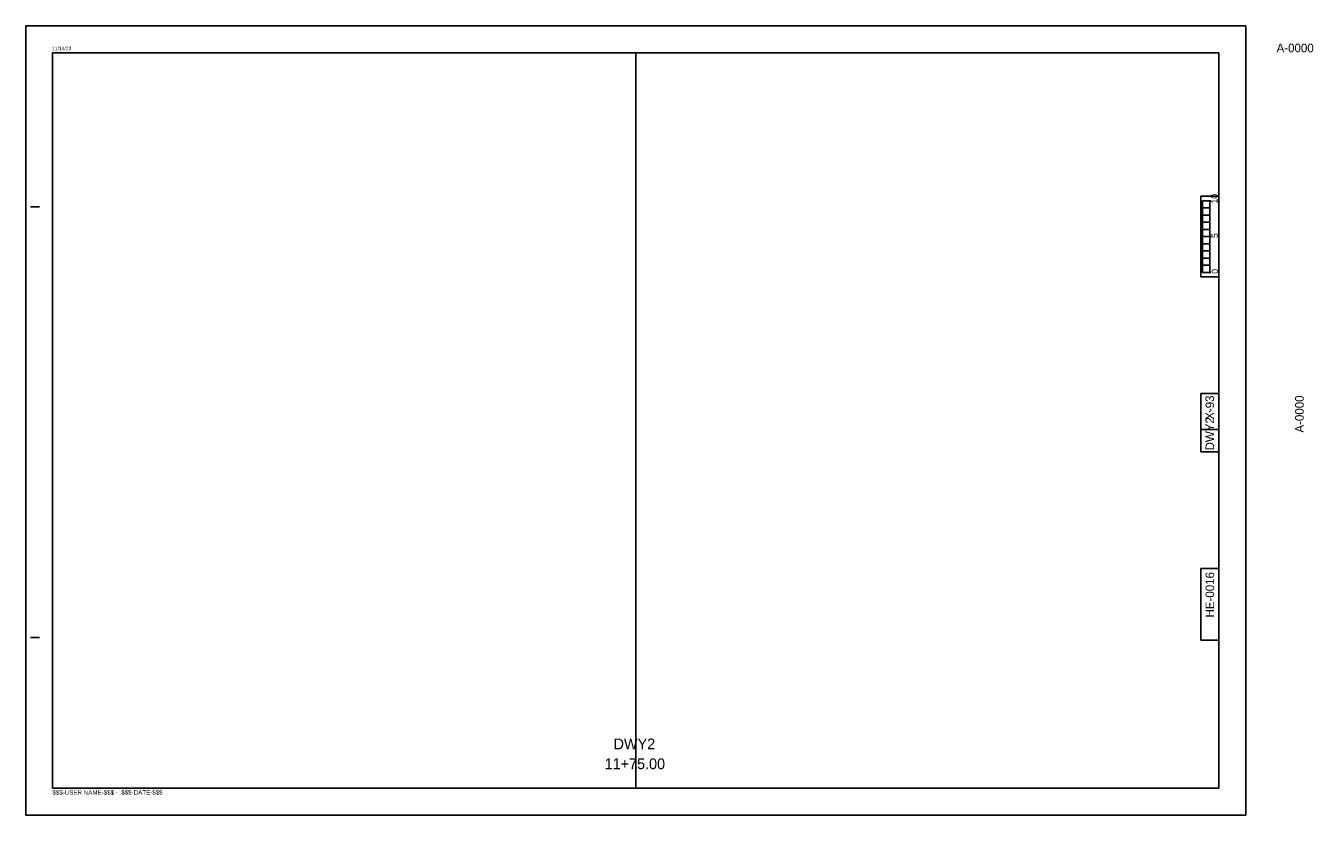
# Model space of a CAD drawing. Extents: x -2.69 to 2.99, y 0 to 1.83.
# Drawn here: x 0 to 2.99, y 0 to 1.833 of the extents above; entities that cross this region are included whole.
import ezdxf

# ---------------------------------------------------------------- set-up
doc = ezdxf.new("R2010")
doc.units = 0
for name, color, linetype in [('P_NCDOT_XS_Sheet_Alignment_Station_Label', 7, 'Continuous'), ('Sheet_Cross_Section_Scale_CELL', 7, 'Continuous'), ('Sheet_Plan_CELL', 7, 'Continuous'), ('Sheet_RDY_XS_Number', 7, 'Continuous'), ('Sheet_RDY_XS_Project_Number', 7, 'Continuous'), ('z - Construction', 7, 'Continuous')]:
    doc.layers.add(name, color=color, linetype=linetype)

msp = doc.modelspace()

# ---------------------------------------------------------------- linework, layer by layer
at = {"layer": 'Sheet_Cross_Section_Scale_CELL'}
for p, q in [((2.7333, 1.4271), (2.7522, 1.4271)), ((2.7333, 1.4271), (2.7333, 1.2604)), ((2.7417, 1.4271), (2.7504, 1.4271)), ((2.75, 1.4271), (2.75, 1.2604)), ((2.7333, 1.3437), (2.7522, 1.3437)), ((2.7333, 1.2604), (2.7522, 1.2604)), ((2.7417, 1.2604), (2.7504, 1.2604))]:
    msp.add_line(p, q, dxfattribs=at)
for points in [[(2.7333, 1.4271), (2.75, 1.4271), (2.75, 1.4104), (2.7333, 1.4104)], [(2.7333, 1.3937), (2.75, 1.3937), (2.75, 1.3771), (2.7333, 1.3771)], [(2.7333, 1.3604), (2.75, 1.3604), (2.75, 1.3437), (2.7333, 1.3437)], [(2.7333, 1.3271), (2.75, 1.3271), (2.75, 1.3104), (2.7333, 1.3104)], [(2.7333, 1.2937), (2.75, 1.2937), (2.75, 1.2771), (2.7333, 1.2771)]]:
    msp.add_lwpolyline(points, close=True, dxfattribs=at)
at = {"layer": 'Sheet_Plan_CELL'}
for p, q in [((0.0625, 1.7708), (0.0625, 0.0625)), ((2.7708, 1.7708), (0.0625, 1.7708)), ((0.1027, 1.7844), (0.1027, 1.7844)), ((2.7708, 1.7708), (2.7708, 0.0625)), ((2.7292, 1.4375), (2.7292, 1.25)), ((2.7292, 1.4375), (2.7708, 1.4375)), ((0.0108, 1.4125), (0.0317, 1.4126)), ((2.7292, 1.25), (2.7708, 1.25)), ((2.7292, 0.9792), (2.7292, 0.8442)), ((2.7708, 0.9792), (2.7292, 0.9792)), ((2.7708, 0.8958), (2.7292, 0.8958)), ((2.7708, 0.8442), (2.7292, 0.8442)), ((2.7292, 0.5729), (2.7292, 0.4062)), ((2.7708, 0.5729), (2.7292, 0.5729)), ((0.0109, 0.4125), (0.0317, 0.4125)), ((2.7708, 0.4062), (2.7292, 0.4062)), ((0.0625, 0.0625), (2.7708, 0.0625))]:
    msp.add_line(p, q, dxfattribs=at)
at = {"layer": 'z - Construction'}
for p, q in [((2.8333, 1.8333), (0, 1.8333)), ((0, 1.8333), (0, 0)), ((2.8333, 0), (2.8333, 1.8333)), ((1.4167, 1.7708), (1.4166, 0.0625)), ((0, 0), (2.8333, 0))]:
    msp.add_line(p, q, dxfattribs=at)
for centre in [(2.7499, 1.3437), (2.7499, 0.9375), (2.7499, 0.875), (2.75, 0.4897)]:
    msp.add_circle(centre, 0.0001, dxfattribs=at)

# ---------------------------------------------------------------- texts
at = {"layer": 'P_NCDOT_XS_Sheet_Alignment_Station_Label'}
for s, p in [('DWY2', (1.3652, 0.1531)), ('11+75.00', (1.3445, 0.107))]:
    msp.add_text(s, height=0.025, dxfattribs=at).set_placement(p)
at = {"layer": 'Sheet_Cross_Section_Scale_CELL'}
for s, p in [('10', (2.7679, 1.4206)), ('5', (2.7689, 1.3404)), ('0', (2.7691, 1.2573))]:
    msp.add_text(s, height=0.015, rotation=90, dxfattribs=at).set_placement(p)
at = {"layer": 'Sheet_Plan_CELL'}
msp.add_text('11/14/23', height=0.00833, rotation=0, dxfattribs=at).set_placement((0.0609, 1.7764))
for s, height, p in [('$$$-USER NAME-$$$', 0.010417, (0.0619, 0.0477)), ('-', 0.0104, (0.2081, 0.0487)), ('$$$-DATE-$$$', 0.010417, (0.2218, 0.0479))]:
    msp.add_text(s, height=height, dxfattribs=at).set_placement(p)
at = {"layer": 'Sheet_RDY_XS_Number'}
for s, p in [('X-93', (2.7599, 0.9183)), ('DWY2', (2.76, 0.8472)), ('HE-0016', (2.7601, 0.4592))]:
    msp.add_text(s, height=0.02, rotation=90, dxfattribs=at).set_placement(p)
at = {"layer": 'Sheet_RDY_XS_Project_Number'}
msp.add_text('A-0000', height=0.02, dxfattribs=at).set_placement((2.9051, 1.7717))
msp.add_text('A-0000', height=0.02, rotation=90, dxfattribs=at).set_placement((2.9681, 0.8886))

doc.saveas('drawing.dxf')
